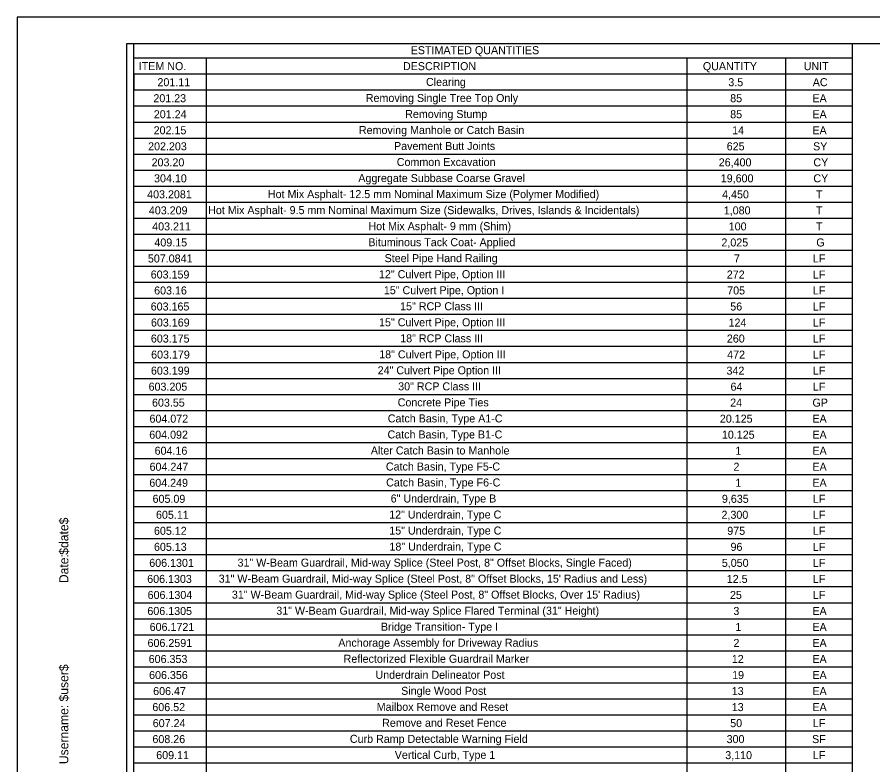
# Model space of a CAD drawing. Extents: x -0.13 to 2.7, y -0.05 to 1.78.
# Drawn here: x -0.135 to 0.917, y 0.864 to 1.782 of the extents above; entities that cross this region are included whole.
import ezdxf

# ---------------------------------------------------------------- set-up
doc = ezdxf.new("R2010")
doc.units = 0
for name, color, linetype in [('ANNOTATION', 7, 'Continuous'), ('BORDER', 7, 'Continuous'), ('Default', 7, 'Continuous'), ('PLOT BOUNDARY', 7, 'Continuous')]:
    doc.layers.add(name, color=color, linetype=linetype)

msp = doc.modelspace()

# ---------------------------------------------------------------- linework, layer by layer
at = {"layer": 'BORDER'}
for p, q in [((0.0088, 1.7323), (0.8921, 1.7323)), ((0.0974, 1.7323), (0.0974, -0.0001)), ((0.6887, 1.7323), (0.6887, -0.0001)), ((0.8101, 1.7323), (0.8101, -0.0001)), ((0.0088, 1.7126), (0.8921, 1.7126)), ((0.0088, 1.6929), (0.8921, 1.6929)), ((0.0088, 1.6732), (0.8921, 1.6732)), ((0.0088, 1.6535), (0.8921, 1.6535)), ((0.0088, 1.6338), (0.8921, 1.6338)), ((0.0088, 1.6141), (0.8921, 1.6141)), ((0.0088, 1.5945), (0.8921, 1.5945)), ((0.0088, 1.5748), (0.8921, 1.5748)), ((0.0088, 1.5551), (0.8921, 1.5551)), ((0.0088, 1.5354), (0.8921, 1.5354)), ((0.0088, 1.5157), (0.8921, 1.5157)), ((0.0088, 1.496), (0.8921, 1.496)), ((0.0088, 1.4763), (0.8921, 1.4763)), ((0.0088, 1.4566), (0.8921, 1.4566)), ((0.0088, 1.437), (0.8921, 1.437)), ((0.0088, 1.4173), (0.8921, 1.4173)), ((0.0088, 1.3976), (0.8921, 1.3976)), ((0.0088, 1.3779), (0.8921, 1.3779)), ((0.0088, 1.3582), (0.8921, 1.3582)), ((0.0088, 1.3385), (0.8921, 1.3385)), ((0.0088, 1.3188), (0.8921, 1.3188)), ((0.0088, 1.2992), (0.8921, 1.2992)), ((0.0088, 1.2795), (0.8921, 1.2795)), ((0.0088, 1.2598), (0.8921, 1.2598)), ((0.0088, 1.2401), (0.8921, 1.2401)), ((0.0088, 1.2204), (0.8921, 1.2204)), ((0.0088, 1.2007), (0.8921, 1.2007)), ((0.0088, 1.181), (0.8921, 1.181)), ((0.0088, 1.1614), (0.8921, 1.1614)), ((0.0088, 1.1417), (0.8921, 1.1417)), ((0.0088, 1.122), (0.8921, 1.122)), ((0.0088, 1.1023), (0.8921, 1.1023)), ((0.0088, 1.0826), (0.8921, 1.0826)), ((0.0088, 1.0629), (0.8921, 1.0629)), ((0.0088, 1.0432), (0.8921, 1.0432)), ((0.0088, 1.0236), (0.8921, 1.0236)), ((0.0088, 1.0039), (0.8921, 1.0039)), ((0.0088, 0.9842), (0.8921, 0.9842)), ((0.0088, 0.9645), (0.8921, 0.9645)), ((0.0088, 0.9448), (0.8921, 0.9448)), ((0.0088, 0.9251), (0.8921, 0.9251)), ((0.0088, 0.9054), (0.8921, 0.9054)), ((0.0088, 0.8858), (0.8921, 0.8858)), ((0.0088, 0.8661), (0.8921, 0.8661))]:
    msp.add_line(p, q, dxfattribs=at)
msp.add_lwpolyline([(0, 1.75), (2.6667, 1.75), (2.6667, 0), (0, 0)], close=True, dxfattribs=at)
for points in [[(0.0088, 0), (0.0088, 1.75)], [(0.8921, 1.75), (0.8921, 0)]]:
    msp.add_lwpolyline(points, dxfattribs=at)
at = {"layer": 'Default'}
msp.add_line((0.0088, 1.7126), (0.0088, 1.6929), dxfattribs=at)
at = {"layer": 'PLOT BOUNDARY'}
msp.add_lwpolyline([(-0.1349, -0.051), (2.6984, -0.051), (2.6984, 1.7823), (-0.1349, 1.7823)], close=True, dxfattribs=at)

# ---------------------------------------------------------------- texts
at = {"layer": 'ANNOTATION'}
for s, height, p in [('201.11', 0.00984, (0.0377, 1.6975)), ('Clearing', 0.00984, (0.3679, 1.6978)), ('3.5', 0.00984, (0.7397, 1.6975)), ('AC', 0.00984, (0.8435, 1.6975)), ('201.23', 0.00984, (0.0327, 1.6778)), ('Removing Single Tree Top Only', 0.009843, (0.2939, 1.6781)), ('85', 0.00984, (0.742, 1.6778)), ('EA', 0.00984, (0.8431, 1.6778)), ('201.24', 0.00984, (0.0332, 1.6581)), ('Removing Stump', 0.009843, (0.3423, 1.6584)), ('85', 0.00984, (0.742, 1.6581)), ('EA', 0.00984, (0.8431, 1.6581)), ('202.15', 0.00984, (0.033, 1.6384)), ('Removing Manhole or Catch Basin', 0.009843, (0.2854, 1.6387)), ('14', 0.00984, (0.7444, 1.6384)), ('EA', 0.00984, (0.8431, 1.6384)), ('202.203', 0.00984, (0.0262, 1.6187)), ('Pavement Butt Joints', 0.009843, (0.3286, 1.6191)), ('625', 0.00984, (0.7377, 1.6187)), ('SY', 0.00984, (0.8439, 1.6187)), ('203.20', 0.00984, (0.0305, 1.599)), ('Common Excavation', 0.009843, (0.332, 1.5994)), ('26,400', 0.00984, (0.7279, 1.599)), ('CY', 0.00984, (0.8443, 1.599)), ('304.10', 0.00984, (0.0335, 1.5794)), ('Aggregate Subbase Coarse Gravel', 0.009843, (0.2847, 1.5797)), ('19,600', 0.00984, (0.7304, 1.5794)), ('CY', 0.00984, (0.8443, 1.5794)), ('403.2081', 0.00984, (0.025, 1.5597)), ('Hot Mix Asphalt- 12.5 mm Nominal Maximum Size (Polymer Modified)', 0.009843, (0.1735, 1.56)), ('4,450', 0.00984, (0.7321, 1.5597)), ('T', 0.00984, (0.8475, 1.5597)), ('403.209', 0.00984, (0.0271, 1.54)), ('Hot Mix Asphalt- 9.5 mm Nominal Maximum Size (Sidewalks, Drives, Islands & Incidentals)', 0.009843, (0.1, 1.5403)), ('1,080', 0.00984, (0.7341, 1.54)), ('T', 0.00984, (0.8475, 1.54)), ('403.211', 0.00984, (0.0312, 1.5203)), ('Hot Mix Asphalt- 9 mm (Shim)', 0.009843, (0.2971, 1.5206)), ('100', 0.00984, (0.7402, 1.5203)), ('T', 0.00984, (0.8475, 1.5203)), ('409.15', 0.00984, (0.0339, 1.5006)), ('Bituminous Tack Coat- Applied', 0.009843, (0.297, 1.5009)), ('2,025', 0.00984, (0.7312, 1.5006)), ('G', 0.00984, (0.8479, 1.5006)), ('507.0841', 0.00984, (0.0259, 1.4809)), ('Steel Pipe Hand Railing', 0.009843, (0.317, 1.4813)), ('7', 0.00984, (0.7466, 1.4809)), ('LF', 0.00984, (0.8437, 1.4809)), ('603.159', 0.00984, (0.0294, 1.4612)), ('12" Culvert Pipe, Option III', 0.009843, (0.3101, 1.4616)), ('272', 0.00984, (0.7378, 1.4612)), ('LF', 0.00984, (0.8437, 1.4612)), ('15" Culvert Pipe, Option I', 0.009843, (0.3161, 1.4419)), ('603.16', 0.00984, (0.0336, 1.4416)), ('705', 0.00984, (0.7383, 1.4416)), ('LF', 0.00984, (0.8437, 1.4416)), ('603.165', 0.00984, (0.0294, 1.4219)), ('15" RCP Class III', 0.009843, (0.3361, 1.4222)), ('56', 0.00984, (0.7421, 1.4219)), ('LF', 0.00984, (0.8437, 1.4219)), ('603.169', 0.00984, (0.0297, 1.4022)), ('15" Culvert Pipe, Option III', 0.009843, (0.3102, 1.4025)), ('124', 0.00984, (0.74, 1.4022)), ('LF', 0.00984, (0.8437, 1.4022)), ('603.175', 0.00984, (0.0296, 1.3825)), ('18" RCP Class III', 0.009843, (0.3362, 1.3828)), ('260', 0.00984, (0.7379, 1.3825)), ('LF', 0.00984, (0.8437, 1.3825)), ('603.179', 0.00984, (0.0299, 1.3628)), ('18" Culvert Pipe, Option III', 0.009843, (0.3104, 1.3631)), ('472', 0.00984, (0.7383, 1.3628)), ('LF', 0.00984, (0.8437, 1.3628)), ('603.199', 0.00984, (0.0297, 1.3431)), ('24" Culvert Pipe Option III', 0.009843, (0.3085, 1.3435)), ('342', 0.00984, (0.7375, 1.3431)), ('LF', 0.00984, (0.8437, 1.3431)), ('603.205', 0.00984, (0.0268, 1.3234)), ('30" RCP Class III', 0.009843, (0.3337, 1.3238)), ('64', 0.00984, (0.7424, 1.3234)), ('LF', 0.00984, (0.8437, 1.3234)), ('603.55', 0.00984, (0.031, 1.3038)), ('Concrete Pipe Ties', 0.009843, (0.3331, 1.3041)), ('24', 0.00984, (0.742, 1.3038)), ('GP', 0.00984, (0.8432, 1.3038)), ('Catch Basin, Type A1-C', 0.009843, (0.3209, 1.2844)), ('604.072', 0.00984, (0.0279, 1.2841)), ('20.125', 0.00984, (0.7293, 1.2841)), ('EA', 0.00984, (0.8431, 1.2841)), ('604.092', 0.00984, (0.0276, 1.2644)), ('Catch Basin, Type B1-C', 0.009843, (0.3206, 1.2647)), ('10.125', 0.00984, (0.7318, 1.2644)), ('EA', 0.00984, (0.8431, 1.2644)), ('604.16', 0.00984, (0.0342, 1.2447)), ('Alter Catch Basin to Manhole', 0.009843, (0.3001, 1.245)), ('1', 0.00984, (0.7484, 1.2447)), ('EA', 0.00984, (0.8431, 1.2447)), ('604.247', 0.00984, (0.028, 1.225)), ('Catch Basin, Type F5-C', 0.009843, (0.3186, 1.2253)), ('2', 0.00984, (0.746, 1.225)), ('EA', 0.00984, (0.8431, 1.225)), ('604.249', 0.00984, (0.0277, 1.2053)), ('Catch Basin, Type F6-C', 0.009843, (0.3189, 1.2057)), ('1', 0.00984, (0.7484, 1.2053)), ('EA', 0.00984, (0.8431, 1.2053)), ('605.09', 0.00984, (0.0317, 1.1856)), ('6" Underdrain, Type B', 0.009843, (0.3245, 1.186)), ('9,635', 0.00984, (0.7318, 1.1856)), ('LF', 0.00984, (0.8437, 1.1856)), ('605.11', 0.00984, (0.0359, 1.166)), ('12" Underdrain, Type C', 0.009843, (0.3227, 1.1663)), ('2,300', 0.00984, (0.7313, 1.166)), ('LF', 0.00984, (0.8437, 1.166)), ('605.12', 0.00984, (0.0334, 1.1463)), ('15" Underdrain, Type C', 0.009843, (0.3228, 1.1466)), ('975', 0.00984, (0.7384, 1.1463)), ('LF', 0.00984, (0.8437, 1.1463)), ('605.13', 0.00984, (0.0334, 1.1266)), ('18" Underdrain, Type C', 0.009843, (0.323, 1.1269)), ('96', 0.00984, (0.7424, 1.1266)), ('LF', 0.00984, (0.8437, 1.1266)), ('606.1301', 0.00984, (0.0276, 1.1069)), ('31" W-Beam Guardrail, Mid-way Splice (Steel Post, 8" Offset Blocks, Single Faced)', 0.009843, (0.1362, 1.1072)), ('5,050', 0.00984, (0.7317, 1.1069)), ('LF', 0.00984, (0.8437, 1.1069)), ('606.1303', 0.00984, (0.0251, 1.0872)), ('31" W-Beam Guardrail, Mid-way Splice (Steel Post, 8" Offset Blocks, 15\' Radius and Less)', 0.009843, (0.113, 1.0875)), ('12.5', 0.00984, (0.7378, 1.0872)), ('LF', 0.00984, (0.8437, 1.0872)), ('606.1304', 0.00984, (0.0256, 1.0675)), ('31" W-Beam Guardrail, Mid-way Splice (Steel Post, 8" Offset Blocks, Over 15\' Radius)', 0.009843, (0.1292, 1.0679)), ('25', 0.00984, (0.7417, 1.0675)), ('LF', 0.00984, (0.8437, 1.0675)), ('606.1305', 0.00984, (0.0253, 1.0478)), ('31" W-Beam Guardrail, Mid-way Splice Flared Terminal (31" Height)', 0.009843, (0.1838, 1.0482)), ('3', 0.00984, (0.7459, 1.0478)), ('EA', 0.00984, (0.8431, 1.0478)), ('606.1721', 0.00984, (0.0281, 1.0282)), ('Bridge Transition- Type I', 0.009843, (0.3125, 1.0285)), ('1', 0.00984, (0.7484, 1.0282)), ('EA', 0.00984, (0.8431, 1.0282)), ('606.2591', 0.00984, (0.0255, 1.0085)), ('Anchorage Assembly for Driveway Radius', 0.009843, (0.2601, 1.0088)), ('2', 0.00984, (0.746, 1.0085)), ('EA', 0.00984, (0.8431, 1.0085)), ('606.353', 0.00984, (0.0269, 0.9888)), ('Reflectorized Flexible Guardrail Marker', 0.009843, (0.2666, 0.9891)), ('12', 0.00984, (0.744, 0.9888)), ('EA', 0.00984, (0.8431, 0.9888)), ('606.356', 0.00984, (0.0274, 0.9691)), ('Underdrain Delineator Post', 0.009843, (0.3058, 0.9694)), ('19', 0.00984, (0.7444, 0.9691)), ('EA', 0.00984, (0.8431, 0.9691)), ('606.47', 0.00984, (0.0324, 0.9494)), ('Single Wood Post', 0.009843, (0.3374, 0.9497)), ('13', 0.00984, (0.7439, 0.9494)), ('EA', 0.00984, (0.8431, 0.9494)), ('606.52', 0.00984, (0.0314, 0.9297)), ('Mailbox Remove and Reset', 0.009843, (0.3073, 0.93)), ('13', 0.00984, (0.7439, 0.9297)), ('EA', 0.00984, (0.8431, 0.9297)), ('607.24', 0.00984, (0.0319, 0.91)), ('Remove and Reset Fence', 0.009843, (0.314, 0.9104)), ('50', 0.00984, (0.742, 0.91)), ('LF', 0.00984, (0.8437, 0.91)), ('608.26', 0.00984, (0.0315, 0.8904)), ('Curb Ramp Detectable Warning Field', 0.009843, (0.2743, 0.8907)), ('300', 0.00984, (0.7376, 0.8904)), ('SF', 0.00984, (0.8427, 0.8904)), ('609.11', 0.00984, (0.0362, 0.8707)), ('Vertical Curb, Type 1', 0.009843, (0.3295, 0.871)), ('3,110', 0.00984, (0.7359, 0.8707)), ('LF', 0.00984, (0.8437, 0.8707))]:
    msp.add_text(s, height=height, dxfattribs=at).set_placement(p)
at = {"layer": 'BORDER'}
for s, height, p in [('ESTIMATED QUANTITIES', 0.009843, (0.3491, 1.7368)), ('ITEM NO.', 0.00984, (0.0147, 1.7172)), ('DESCRIPTION', 0.009843, (0.3396, 1.7172)), ('QUANTITY', 0.00984, (0.7084, 1.7172)), ('UNIT', 0.00984, (0.8324, 1.7172))]:
    msp.add_text(s, height=height, dxfattribs=at).set_placement(p)
for s, p in [('$date$', (-0.0719, 1.1218)), ('Date:', (-0.0719, 1.0869)), ('$user$', (-0.0719, 0.9415)), ('Username:', (-0.0719, 0.8645))]:
    msp.add_text(s, height=0.01116, rotation=90, dxfattribs=at).set_placement(p)

doc.saveas('drawing.dxf')
